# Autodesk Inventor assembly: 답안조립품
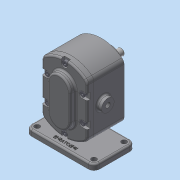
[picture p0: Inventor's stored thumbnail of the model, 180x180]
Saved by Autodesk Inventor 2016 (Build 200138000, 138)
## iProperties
Created: 2019-03
Part Number: 답안조립품
Document SubType Name: Assembly
Designer: 2-PC10
Author: 2-PC10
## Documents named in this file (10)
- C:\Users\2-PC10\Desktop\490308V1002\답안조립품.iam
- C:\Users\2-PC10\Desktop\490308V1002\본체.ipt
- C:\Users\2-PC10\Desktop\490308V1002\메인축.ipt
- C:\Users\2-PC10\Desktop\490308V1002\키 6 x 6 x 18.ipt
- C:\Users\2-PC10\Desktop\490308V1002\베어링부시.ipt
- C:\Users\2-PC10\Desktop\490308V1002\서브축.ipt
- C:\Users\2-PC10\Desktop\490308V1002\스퍼기어.ipt
- C:\Users\2-PC10\Desktop\490308V1002\오일 실 16 28 7.ipt
- C:\Users\2-PC10\Desktop\490308V1002\커버.ipt
- C:\Users\2-PC10\Desktop\490308V1002\볼트 M5.ipt
